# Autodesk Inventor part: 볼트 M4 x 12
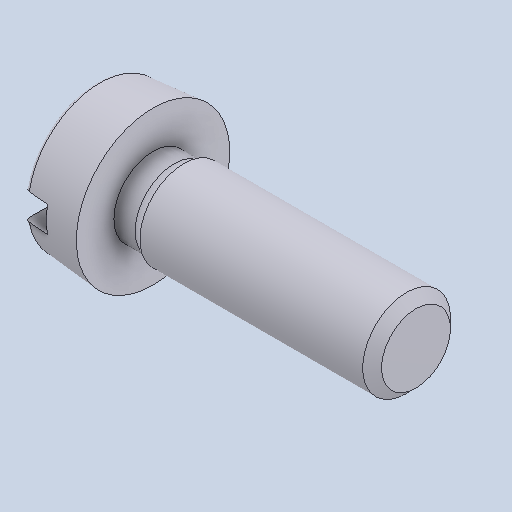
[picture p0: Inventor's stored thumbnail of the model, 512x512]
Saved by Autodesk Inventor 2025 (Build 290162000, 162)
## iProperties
Created: 2024-07
Part Number: 볼트 M4 x 12
Material: 강철, 연강
Description: 6각머리 태핑 나사
Document SubType Name: Modeling
Designer: myung
Density: 7.85 g/cm^3
Appearance: 기본값
Author: jhkim
Sending System: Autodesk Inventor 2025
Preprocessor: ST-DEVELOPER v20
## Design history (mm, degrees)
feature "Solid1"
node "솔리드1"
